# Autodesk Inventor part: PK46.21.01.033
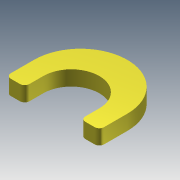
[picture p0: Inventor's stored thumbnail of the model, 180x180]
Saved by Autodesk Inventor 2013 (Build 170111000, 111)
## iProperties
Created: 2005-04
Part Number: PK46.21.01.033
Material: Steel, Mild
Document SubType Name: Modeling
Designer: salex
Manufacturer: Standard
Standards Organization: Custom
Density: 7.86 g/cm^3
Author: salex
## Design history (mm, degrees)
sketch "Эскиз1"
  geometry: L1 (-29.998, 0)-(-29.998, -20); L2 (-29.998, -20)-(-49.998, -20); L3 (-49.998, -20)-(-49.998, 10); L4 (30.002, 0)-(30.002, -20); L5 (30.002, -20)-(50.002, -20); L6 (50.002, -20)-(50.002, 10); A1 r 30 centre (0.002, 0) between (30.002, 0) and (-29.998, 0); A2 r 50 centre (0.002, 10) between (50.002, 10) and (-49.998, 10)
  constraints: 12 end point, 4 point on circle, 4 tangent, 3 parallel, 2 centre point, 2 collinear, 2 perpendicular, 1 vertical, 1 other
  dimensions: "d0" = 10 distance of A1.centre A2.centre; "d1" = 20 distance from line of A1.centre L2; "d2" = 30 radius of A1; "d3" = 50 radius of A2
extrude "Выдавливание1" new body sketch "Эскиз1" distance "d4" = 16; taper "d5" = 0 deg
fillet "Сопряжение1" dims "d6" = 5
body "Solid1"
